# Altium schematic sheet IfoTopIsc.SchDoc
size A; DocumentNumber: 1; SheetNumber: 1; SheetTotal: 11; pInstance: Corner
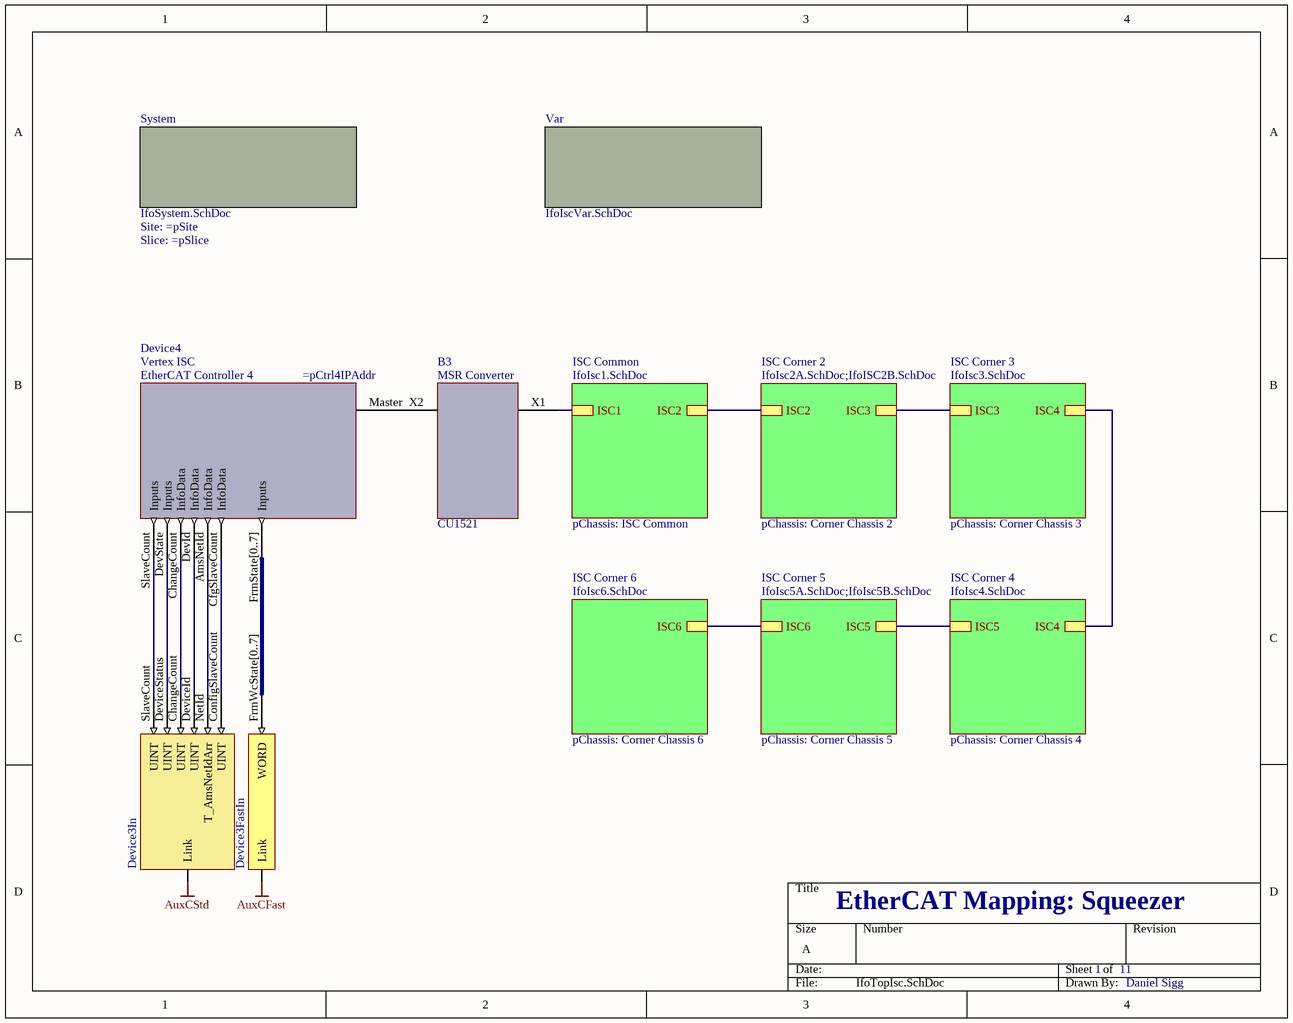
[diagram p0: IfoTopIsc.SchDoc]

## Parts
B3  MSR Converter  Part Number: CU1521  (mechanical)
Device4  Vertex ISC  DeviceDesc: EtherCAT Controller 4  (mechanical)
V87  Device3In  (no BOM)
V88  Device3FastIn  (no BOM)

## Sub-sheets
ISC Common = IfoIsc1.SchDoc: ISC1, ISC2  | pChassis: ISC Common
ISC Corner 2 = IfoIsc2A.SchDoc;IfoISC2B.SchDoc: ISC2, ISC3  | pChassis: Corner Chassis 2
ISC Corner 3 = IfoIsc3.SchDoc: ISC3, ISC4  | pChassis: Corner Chassis 3
ISC Corner 4 = IfoIsc4.SchDoc: ISC4, ISC5  | pChassis: Corner Chassis 4
ISC Corner 5 = IfoIsc5A.SchDoc;IfoIsc5B.SchDoc: ISC5, ISC6  | pChassis: Corner Chassis 5
ISC Corner 6 = IfoIsc6.SchDoc: ISC6  | pChassis: Corner Chassis 6
System = IfoSystem.SchDoc: no entries  | Site: =pSite; Slice: =pSlice
Var = IfoIscVar.SchDoc: no entries

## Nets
AuxCFast: V88.?1(Link)
AuxCStd: V87.?1(Link)
NetB3_X1: B3.X1(B) ; sheet ISC Common/ISC1
NetB3_X2: B3.X2(A) Device4.Master(B)
NetDevice4_AmsNetId: Device4.AmsNetId(InfoData) V87.NetId(T_AmsNetIdArr)
NetDevice4_CfgSlaveCount: Device4.CfgSlaveCount(InfoData) V87.ConfigSlaveCount(UINT)
NetDevice4_ChangeCount: Device4.ChangeCount(InfoData) V87.ChangeCount(UINT)
NetDevice4_DevId: Device4.DevId(InfoData) V87.DeviceId(UINT)
NetDevice4_DevState: Device4.DevState(Inputs) V87.DeviceStatus(UINT)
NetDevice4_FrmState[0..7]: Device4.FrmState[0..7](Inputs) V88.FrmWcState[0..7](WORD)
NetDevice4_SlaveCount: Device4.SlaveCount(Inputs) V87.SlaveCount(UINT)
(unnamed): sheet ISC Common/ISC2, sheet ISC Corner 2/ISC2
(unnamed): sheet ISC Corner 2/ISC3, sheet ISC Corner 3/ISC3  [a separate net that carries the same name]
(unnamed): sheet ISC Corner 3/ISC4, sheet ISC Corner 4/ISC4  [a separate net that carries the same name]
(unnamed): sheet ISC Corner 4/ISC5, sheet ISC Corner 5/ISC5  [a separate net that carries the same name]
(unnamed): sheet ISC Corner 5/ISC6, sheet ISC Corner 6/ISC6  [a separate net that carries the same name]

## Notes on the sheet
- EtherCAT Mapping: Squeezer
- Daniel Sigg

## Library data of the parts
B3 = MediaConverterCAT5toFiber: EtherCAT Media Converter; BoxType: Box; BoxNextB: SGTCQRGF; BoxPrev: DMJNXSST; PortPrevFull: 1000/; Fullname: TIID^Vertex ISC (EtherCAT)^MSR Converter (CU1521); BoxAddr: 1001; Disabled: False
Device4 = EtherCATMaster: EtherCAT Master; Part Number: FC9022; DeviceData: 0001053F990A; BoxNextB: IQKGWTEC; Fullname: TIID^Vertex ISC (EtherCAT); BoxSubType: 111; Disabled: False
V87 = PLCInfo_MasterInfoInStruct: MasterInfoInStruct; PLC: H1AuxCorner; Task: AuxCStd; BoxType: Variable; Instance: H1AuxCorner Instance
V88 = PLCInfo_MasterInfoFastInStruct: MasterInfoFastInStruct; PLC: H1AuxCorner; Task: AuxCFast; BoxType: Variable; Instance: H1AuxCorner Instance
